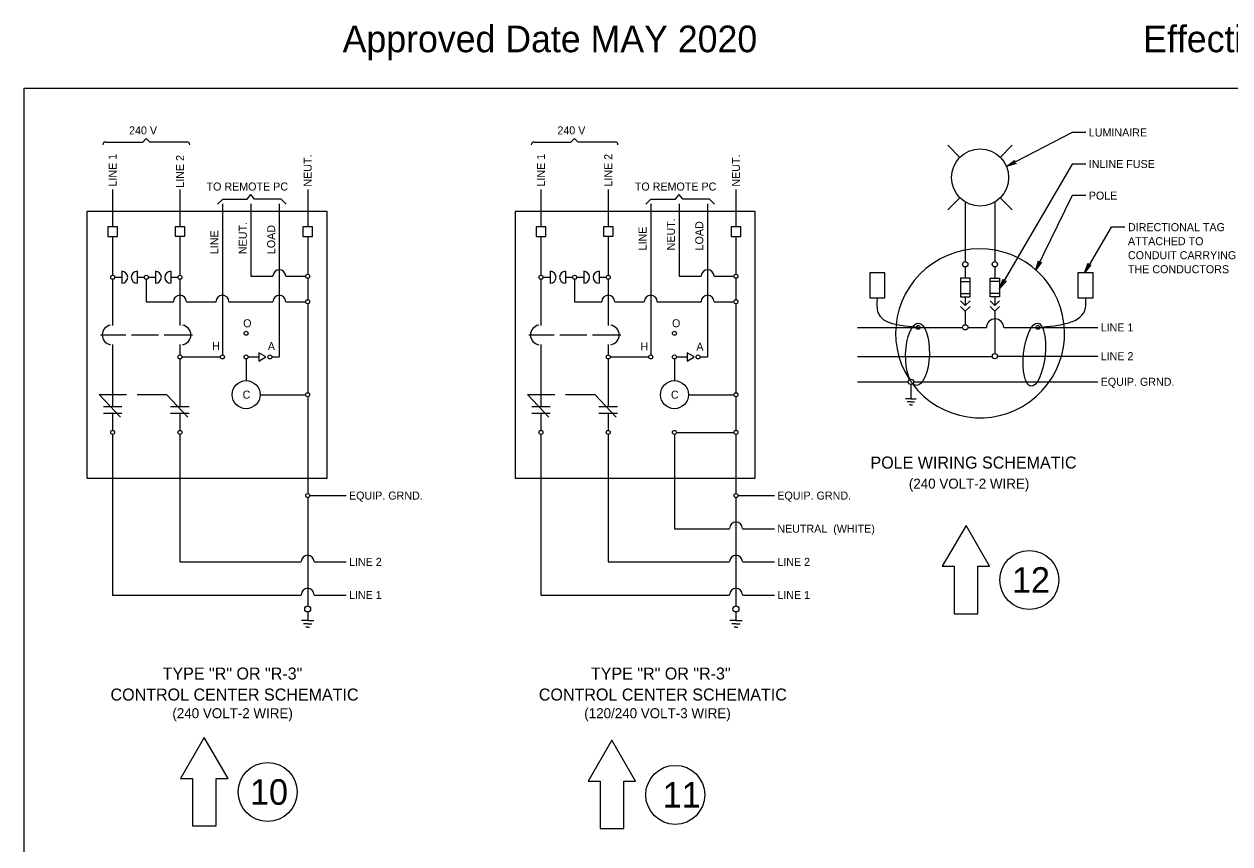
# Model space of a CAD drawing. Extents: x 99981 to 128681, y 99783 to 102182.
# Drawn here: x 120381 to 122189, y 100954 to 102182 of the extents above; entities that cross this region are included whole.
import ezdxf

# ---------------------------------------------------------------- set-up
doc = ezdxf.new("R2010")
doc.units = 0
for name, color, linetype in [('Default', 7, 'Continuous'), ('Level 1', 7, 'Continuous'), ('RD Lighting', 7, 'Continuous'), ('RD Standard Plans Active', 7, 'Continuous')]:
    doc.layers.add(name, color=color, linetype=linetype)

msp = doc.modelspace()

# ---------------------------------------------------------------- linework, layer by layer
at = {"layer": 'Default'}
msp.add_lwpolyline([(120381.4, 102086.3), (123581.1, 102086.3), (123581.1, 99886.7), (120381.4, 99886.7)], close=True, dxfattribs=at)
at = {"layer": 'Level 1'}
for p, q in [((120559.1, 102005.5), (120564.5, 102010.9)), ((120569.8, 102005.5), (120564.5, 102010.9)), ((121201.1, 102005.5), (121206.5, 102010.9)), ((121211.9, 102005.5), (121206.5, 102010.9)), ((121952.2, 102019.8), (121853.8, 101968.7)), ((121972.8, 102019.8), (121952.2, 102019.8)), ((120503.4, 102005.5), (120559.1, 102005.5)), ((120625.5, 102005.5), (120569.8, 102005.5)), ((121145.5, 102005.5), (121201.1, 102005.5)), ((121267.5, 102005.5), (121211.9, 102005.5)), ((121784, 101982.5), (121766, 102000.6)), ((121844.5, 101982.5), (121862.6, 102000.6)), ((121952.2, 101972.5), (121843.5, 101786)), ((121972.8, 101972.5), (121952.2, 101972.5)), ((120514.1, 101934.2), (120514.1, 101878.3)), ((120614.9, 101934.2), (120614.9, 101878.3)), ((120806.4, 101934.2), (120806.4, 101878.3)), ((121156.1, 101934.2), (121156.1, 101878.3)), ((121256.9, 101934.2), (121256.9, 101878.3)), ((121448.4, 101934.2), (121448.4, 101878.3)), ((120671.4, 101912.2), (120679, 101919.8)), ((120679, 101919.8), (120715.6, 101919.8)), ((120715.6, 101919.8), (120721, 101926.8)), ((120726.5, 101919.8), (120721, 101926.8)), ((120766.7, 101919.8), (120726.5, 101919.8)), ((120774.3, 101912.2), (120766.7, 101919.8)), ((121313.4, 101912.2), (121321, 101919.8)), ((121321, 101919.8), (121357.6, 101919.8)), ((121357.6, 101919.8), (121363, 101926.8)), ((121368.5, 101919.8), (121363, 101926.8)), ((121408.7, 101919.8), (121368.5, 101919.8)), ((121416.3, 101912.2), (121408.7, 101919.8)), ((121766, 101903.9), (121784, 101922)), ((121862.6, 101903.9), (121844.5, 101922)), ((121952.2, 101925.2), (121897.8, 101813.9)), ((121972.8, 101925.2), (121952.2, 101925.2)), ((120678.7, 101912.9), (120678.7, 101686.4)), ((120721.3, 101912.9), (120721.3, 101804.3)), ((120763.9, 101912.9), (120763.9, 101683.4)), ((121320.7, 101912.9), (121320.7, 101686.4)), ((121363.3, 101912.9), (121363.3, 101804.3)), ((121405.9, 101912.9), (121405.9, 101683.4)), ((121792.1, 101915.7), (121792.1, 101826.3)), ((121836.4, 101915.7), (121836.4, 101826.3)), ((120514.1, 101863.9), (120514.1, 101805.8)), ((120614.9, 101864.2), (120614.9, 101805.8)), ((120806.4, 101864.2), (120806.4, 101807.3)), ((121156.1, 101863.9), (121156.1, 101805.8)), ((121256.9, 101864.2), (121256.9, 101805.8)), ((121448.4, 101864.2), (121448.4, 101807.3)), ((122011, 101877.9), (121970.7, 101809.7)), ((122031.5, 101877.9), (122011, 101877.9)), ((120527.7, 101811.8), (120527.7, 101793.9)), ((120550.9, 101811.8), (120550.9, 101793.9)), ((120578.1, 101811.8), (120578.1, 101793.9)), ((120601.2, 101811.8), (120601.2, 101793.9)), ((121169.8, 101811.8), (121169.8, 101793.9)), ((121192.9, 101811.8), (121192.9, 101793.9)), ((121220.1, 101811.8), (121220.1, 101793.9)), ((121243.2, 101811.8), (121243.2, 101793.9)), ((121792.1, 101818.3), (121792.1, 101801.8)), ((121836.4, 101818.3), (121836.4, 101801.8)), ((120514.1, 101799.9), (120514.1, 101730.5)), ((120517.1, 101802.8), (120527.7, 101802.8)), ((120550.9, 101802.8), (120561.5, 101802.8)), ((120564.5, 101799.9), (120564.5, 101766.2)), ((120567.5, 101802.8), (120578.1, 101802.8)), ((120601.2, 101802.8), (120611.9, 101802.8)), ((120614.9, 101799.9), (120614.9, 101730.5)), ((120721.3, 101804.3), (120754.1, 101804.3)), ((120773.7, 101804.3), (120803.4, 101804.3)), ((120806.4, 101801.3), (120806.4, 101769.2)), ((121156.1, 101799.9), (121156.1, 101730.5)), ((121159.1, 101802.8), (121169.8, 101802.8)), ((121192.9, 101802.8), (121203.5, 101802.8)), ((121206.5, 101799.9), (121206.5, 101766.2)), ((121209.5, 101802.8), (121220.1, 101802.8)), ((121243.2, 101802.8), (121253.9, 101802.8)), ((121256.9, 101799.9), (121256.9, 101730.5)), ((121363.3, 101804.3), (121396.1, 101804.3)), ((121415.7, 101804.3), (121445.5, 101804.3)), ((121448.4, 101801.3), (121448.4, 101769.2)), ((121785, 101796.4), (121799.2, 101796.4)), ((121843.5, 101796.4), (121829.3, 101796.4)), ((121785, 101778.4), (121799.2, 101778.4)), ((121792.1, 101773.3), (121792.1, 101760.6)), ((121843.5, 101778.4), (121829.3, 101778.4)), ((121836.4, 101773.3), (121836.4, 101760.6)), ((120564.5, 101766.2), (120605.1, 101766.2)), ((120624.6, 101766.2), (120669, 101766.2)), ((120688.4, 101766.2), (120754.1, 101766.2)), ((120773.6, 101766.2), (120803.4, 101766.2)), ((120806.4, 101763.2), (120806.4, 101629.9)), ((121206.5, 101766.2), (121247.1, 101766.2)), ((121266.6, 101766.2), (121311, 101766.2)), ((121330.5, 101766.2), (121396.1, 101766.2)), ((121415.6, 101766.2), (121445.5, 101766.2)), ((121448.4, 101763.2), (121448.4, 101629.9)), ((121792.1, 101752.1), (121792.1, 101731.7)), ((121836.4, 101752.1), (121836.4, 101688.5)), ((121630.6, 101727.6), (121788.2, 101727.6)), ((121796.1, 101727.6), (121823.8, 101727.6)), ((121849.7, 101727.6), (121990.6, 101727.6)), ((120496, 101716.4), (120533.9, 101716.4)), ((120514.1, 101702.2), (120514.1, 101609.2)), ((120542.5, 101716.4), (120583, 101716.4)), ((120591.4, 101716.4), (120633.8, 101716.4)), ((120614.9, 101702.2), (120614.9, 101686.4)), ((121138, 101716.4), (121175.9, 101716.4)), ((121156.1, 101702.2), (121156.1, 101609.2)), ((121184.5, 101716.4), (121225, 101716.4)), ((121233.4, 101716.4), (121275.8, 101716.4)), ((121256.9, 101702.2), (121256.9, 101686.4)), ((120617.8, 101683.4), (120675.7, 101683.4)), ((120717.2, 101683.4), (120733.2, 101683.4)), ((120752.6, 101683.4), (120763.9, 101683.4)), ((121259.8, 101683.4), (121317.7, 101683.4)), ((121359.2, 101683.4), (121375.2, 101683.4)), ((121394.7, 101683.4), (121405.9, 101683.4)), ((121630.6, 101684.3), (121832.5, 101684.3)), ((121840.4, 101684.6), (121990.6, 101684.6)), ((120614.9, 101680.5), (120614.9, 101609.2)), ((120714.2, 101680.5), (120714.2, 101647.9)), ((121256.9, 101680.5), (121256.9, 101609.2)), ((121356.2, 101680.5), (121356.2, 101647.9)), ((121630.6, 101646.2), (121706.7, 101646.2)), ((121714.6, 101646.2), (121990.6, 101646.2)), ((120494.1, 101627.2), (120525.9, 101593.3)), ((120494.1, 101627.2), (120534.9, 101627.2)), ((120550.7, 101627.2), (120594.8, 101627.2)), ((120594.8, 101627.2), (120626.6, 101593.3)), ((120735.2, 101626.9), (120803.4, 101626.9)), ((121136.1, 101627.2), (121167.9, 101593.3)), ((121136.1, 101627.2), (121177, 101627.2)), ((121192.7, 101627.2), (121236.8, 101627.2)), ((121236.8, 101627.2), (121268.6, 101593.3)), ((121377.2, 101626.9), (121445.5, 101626.9)), ((121710.7, 101642.2), (121710.7, 101620.5)), ((120500.2, 101609.2), (120528, 101609.2)), ((120600.9, 101609.2), (120628.8, 101609.2)), ((120806.4, 101623.5), (120806.4, 101479.1)), ((121142.2, 101609.2), (121170.1, 101609.2)), ((121242.9, 101609.2), (121270.8, 101609.2)), ((121448.4, 101623.5), (121448.4, 101573.4)), ((121710.6, 101620.5), (121702.6, 101620.5)), ((121710.6, 101616.3), (121705.2, 101616.3)), ((121710.6, 101611.9), (121708.3, 101611.9)), ((121710.7, 101620.5), (121718.7, 101620.5)), ((121710.7, 101616.3), (121716.1, 101616.3)), ((121710.7, 101611.9), (121713, 101611.9)), ((120500.2, 101599.2), (120528, 101599.2)), ((120514.1, 101599.2), (120514.1, 101573.4)), ((120600.9, 101599.2), (120628.8, 101599.2)), ((120614.9, 101599.2), (120614.9, 101573.4)), ((121142.2, 101599.2), (121170.1, 101599.2)), ((121156.1, 101599.2), (121156.1, 101573.4)), ((121242.9, 101599.2), (121270.8, 101599.2)), ((121256.9, 101599.2), (121256.9, 101573.4)), ((120514.1, 101567.4), (120514.1, 101326.7)), ((120614.9, 101567.4), (120614.9, 101376.4)), ((121156.1, 101567.4), (121156.1, 101326.7)), ((121256.9, 101567.4), (121256.9, 101376.4)), ((121356.2, 101567.4), (121356.2, 101426.1)), ((121359.2, 101570.4), (121445.5, 101570.4)), ((121448.4, 101567.4), (121448.4, 101478.7)), ((120806.4, 101472.7), (120806.4, 101310.3)), ((120809.4, 101475.7), (120863.9, 101475.7)), ((121448.4, 101472.7), (121448.4, 101310.3)), ((121451.4, 101475.7), (121505.9, 101475.7)), ((121356.2, 101426.1), (121438.7, 101426.1)), ((121458.1, 101426.1), (121505.9, 101426.1)), ((120614.9, 101376.4), (120796.7, 101376.4)), ((120816.1, 101376.4), (120863.9, 101376.4)), ((121256.9, 101376.4), (121438.7, 101376.4)), ((121458.1, 101376.4), (121505.9, 101376.4)), ((120514.1, 101326.7), (120796.7, 101326.7)), ((120816.1, 101326.7), (120863.9, 101326.7)), ((121156.1, 101326.7), (121438.7, 101326.7)), ((121458.1, 101326.7), (121505.9, 101326.7)), ((120806.4, 101288.3), (120797.2, 101288.4)), ((120806.4, 101283.5), (120800.1, 101283.5)), ((120806.4, 101301.1), (120806.4, 101288.3)), ((120806.4, 101288.3), (120815.7, 101288.3)), ((120806.4, 101283.5), (120812.7, 101283.5)), ((121448.4, 101288.3), (121439.2, 101288.4)), ((121448.4, 101283.5), (121442.1, 101283.5)), ((121448.4, 101301.1), (121448.4, 101288.3)), ((121448.4, 101288.3), (121457.7, 101288.3)), ((121448.4, 101283.5), (121454.7, 101283.5)), ((120806.4, 101278.4), (120803.7, 101278.4)), ((120806.4, 101278.4), (120809.1, 101278.4)), ((121448.4, 101278.4), (121445.7, 101278.4)), ((121448.4, 101278.4), (121451.1, 101278.4))]:
    msp.add_line(p, q, dxfattribs=at)
for points in [[(121868.2, 101973.3), (121853.8, 101968.7), (121865.9, 101977.8), (121865, 101974.5)], [(120475.6, 101501.7), (120835.4, 101501.7), (120835.4, 101901.5), (120475.6, 101901.5)], [(121117.6, 101501.7), (121477.4, 101501.7), (121477.4, 101901.5), (121117.6, 101901.5)], [(120507.1, 101864.1), (120521.3, 101864.1), (120521.3, 101878.2), (120507.1, 101878.2)], [(120607.9, 101864.2), (120622.1, 101864.2), (120622.1, 101878.3), (120607.9, 101878.3)], [(120799.3, 101864), (120813.5, 101864), (120813.5, 101878.2), (120799.3, 101878.2)], [(121149.1, 101864.1), (121163.3, 101864.1), (121163.3, 101878.2), (121149.1, 101878.2)], [(121249.9, 101864.2), (121264.1, 101864.2), (121264.1, 101878.3), (121249.9, 101878.3)], [(121441.3, 101864), (121455.5, 101864), (121455.5, 101878.2), (121441.3, 101878.2)], [(121906.1, 101825.5), (121897.8, 101813.9), (121901.8, 101827.6), (121903, 101824.6)], [(121671.5, 101771.9), (121671.5, 101809.7), (121648.8, 101809.7), (121648.8, 101771.9)], [(121983.6, 101771.9), (121983.6, 101809.7), (121960.9, 101809.7), (121960.9, 101771.9)], [(121980.5, 101821.3), (121970.7, 101809.7), (121976.1, 101823.8), (121977.1, 101820.5)], [(121785, 101773.3), (121799.2, 101773.3), (121799.2, 101801.7), (121785, 101801.7)], [(121843.5, 101773.3), (121829.3, 101773.3), (121829.3, 101801.7), (121843.5, 101801.7)], [(121853.2, 101797.6), (121843.5, 101786), (121848.8, 101800.2), (121849.9, 101796.9)], [(120743.8, 101683.4), (120733.2, 101689.6), (120733.2, 101677.3)], [(121385.8, 101683.4), (121375.2, 101689.6), (121375.2, 101677.3)]]:
    msp.add_lwpolyline(points, close=True, dxfattribs=at)
for points in [[(121785, 101767.7), (121792.1, 101760.6), (121799.2, 101767.7)], [(121785, 101759.2), (121792.1, 101752.1), (121799.2, 101759.2)], [(121843.5, 101767.7), (121836.4, 101760.6), (121829.3, 101767.7)], [(121843.5, 101759.2), (121836.4, 101752.1), (121829.3, 101759.2)]]:
    msp.add_lwpolyline(points, dxfattribs=at)
for centre, radius in [((121814.3, 101952.3), 42.8), ((121792.1, 101822.3), 3.97), ((121836.4, 101822.3), 3.97), ((120514.1, 101802.8), 2.98), ((120564.5, 101802.8), 2.98), ((120614.9, 101802.8), 2.98), ((120806.4, 101804.3), 2.98), ((121156.1, 101802.8), 2.98), ((121206.5, 101802.8), 2.98), ((121256.9, 101802.8), 2.98), ((121448.4, 101804.3), 2.98), ((120806.4, 101766.2), 2.98), ((121448.4, 101766.2), 2.98), ((120714.2, 101718.9), 2.98), ((121356.2, 101718.9), 2.98), ((121721.3, 101727.7), 2.84), ((121792.1, 101727.8), 3.97), ((121901, 101727.7), 2.84), ((120614.9, 101683.4), 2.98), ((120678.7, 101683.4), 2.98), ((120714.2, 101683.4), 2.98), ((120749.7, 101683.4), 2.98), ((121256.9, 101683.4), 2.98), ((121320.7, 101683.4), 2.98), ((121356.2, 101683.4), 2.98), ((121391.7, 101683.4), 2.98), ((121836.4, 101684.6), 3.97), ((120714.2, 101626.9), 21), ((121356.2, 101626.9), 21), ((121710.7, 101646.2), 3.97), ((120806.4, 101626.9), 2.98), ((121448.4, 101626.9), 2.98), ((120514.1, 101570.4), 2.98), ((120614.9, 101570.4), 2.98), ((121156.1, 101570.4), 2.98), ((121256.9, 101570.4), 2.98), ((121356.2, 101570.4), 2.98), ((121448.4, 101570.4), 2.98), ((120806.4, 101475.7), 2.98), ((121448.4, 101475.7), 2.98), ((120806.4, 101305.8), 4.47), ((121448.4, 101305.8), 4.47)]:
    msp.add_circle(centre, radius, dxfattribs=at)
for centre, radius, start, end in [((120503.5, 102001.4), 4.15, 89.2769, 178.8505), ((120625.4, 102001.4), 4.15, 1.1495, 90.7231), ((121145.6, 102001.4), 4.15, 89.2769, 178.8505), ((121267.4, 102001.4), 4.15, 1.1495, 90.7231), ((121814.3, 101718.8), 126.6, 216.8263, 213.2275), ((120527.7, 101802.8), 8.96, 270, 90), ((120550.9, 101802.8), 8.96, 90, 270), ((120578.1, 101802.8), 8.96, 270, 90), ((120601.2, 101802.8), 8.96, 90, 270), ((120763.9, 101804.3), 9.72, 0, 180), ((121169.8, 101802.8), 8.96, 270, 90), ((121192.9, 101802.8), 8.96, 90, 270), ((121220.1, 101802.8), 8.96, 270, 90), ((121243.2, 101802.8), 8.96, 90, 270), ((121405.9, 101804.3), 9.72, 0, 180), ((120614.9, 101766.2), 9.72, 0, 180), ((120678.7, 101766.2), 9.72, 0, 180), ((120763.9, 101766.2), 9.72, 0, 180), ((121256.9, 101766.2), 9.72, 0, 180), ((121320.7, 101766.2), 9.72, 0, 180), ((121405.9, 101766.2), 9.72, 0, 180), ((121836.8, 101727.4), 13, 0, 180), ((120513.3, 101716.4), 14.9, 99.986, 260.014), ((120616.4, 101716.4), 14.9, 279.986, 80.014), ((121155.3, 101716.4), 14.9, 99.986, 260.014), ((121258.4, 101716.4), 14.9, 279.986, 80.014), ((121448.4, 101426.4), 9.72, 0, 180), ((120806.4, 101376.7), 9.72, 0, 180), ((121448.4, 101376.7), 9.72, 0, 180), ((120806.4, 101327.1), 9.72, 0, 180), ((121448.4, 101327.1), 9.72, 0, 180)]:
    msp.add_arc(centre, radius, start, end, dxfattribs=at)
for centre, major_axis, ratio in [((121895.6, 101686.9), (-5.1, -47.3), 0.339542), ((121720.5, 101687.5), (-1.5, -46.7), 0.380534)]:
    msp.add_ellipse(centre, major_axis=major_axis, ratio=ratio, dxfattribs=at)
for points in [[(121721.3, 101727.7), (121661.7, 101749.9), (121660.3, 101770.3)], [(121901, 101727.7), (121972.2, 101756.9), (121972.6, 101770.8)]]:
    msp.add_spline(points, degree=3, dxfattribs=at)
at = {"layer": 'RD Lighting'}
for points in [[(121793.2, 101431.1), (121757.7, 101369.7), (121775.4, 101369.7), (121775.4, 101298.7), (121810.9, 101298.7), (121810.9, 101369.7), (121828.6, 101369.7)], [(120651.5, 101113.4), (120616, 101052), (120633.8, 101052), (120633.8, 100981), (120669.3, 100981), (120669.3, 101052), (120687, 101052)], [(121262.4, 101109.2), (121226.9, 101047.7), (121244.7, 101047.7), (121244.7, 100976.8), (121280.1, 100976.8), (121280.1, 101047.7), (121297.9, 101047.7)]]:
    msp.add_lwpolyline(points, close=True, dxfattribs=at)
for centre in [(121888, 101349.3), (120746.4, 101031.6), (121357.3, 101027.3)]:
    msp.add_circle(centre, 44.2, dxfattribs=at)

# ---------------------------------------------------------------- texts
at = {"layer": 'Level 1'}
for s, height, p in [('240 V', 12, (120538.7, 102016.9)), ('240 V', 12, (121180.7, 102016.9)), (' LUMINAIRE', 12, (121972.8, 102013.8)), (' INLINE FUSE', 12, (121972.8, 101966.5)), ('TO REMOTE PC', 12, (120654.8, 101932.8)), ('TO REMOTE PC', 12, (121296.8, 101932.8)), (' POLE', 12, (121972.8, 101919.2)), (' DIRECTIONAL TAG', 12, (122031.5, 101871.9)), (' ATTACHED TO', 12, (122031.5, 101850.9)), (' CONDUIT CARRYING', 12, (122031.5, 101829.9)), (' THE CONDUCTORS', 12, (122031.5, 101808.9)), ('O', 12, (120709.7, 101727.9)), ('O', 12, (121352.5, 101727.9)), (' LINE 1', 12, (121990.6, 101721.6)), ('H', 12, (120663.2, 101693.7)), ('A', 12, (120746.7, 101693.6)), ('H', 12, (121305.2, 101693.1)), ('A', 12, (121389, 101692.9)), (' LINE 2', 12, (121990.6, 101678.6)), (' EQUIP. GRND.', 12, (121990.6, 101640.2)), ('C', 12, (120708.9, 101620.9)), ('C', 12, (121350.9, 101620.9)), ('POLE WIRING SCHEMATIC', 18, (121650, 101516.2)), ('(240 VOLT-2 WIRE)', 15, (121707.5, 101486.1)), (' EQUIP. GRND.', 12, (120863.9, 101469.7)), (' EQUIP. GRND.', 12, (121505.9, 101469.7)), (' NEUTRAL  (WHITE)', 12, (121505.9, 101420.1)), (' LINE 2', 12, (120863.9, 101370.4)), (' LINE 2', 12, (121505.9, 101370.4)), (' LINE 1', 12, (120863.9, 101320.7)), (' LINE 1', 12, (121505.9, 101320.7)), ('TYPE "R" OR "R-3"', 18, (120589, 101200.1)), ('TYPE "R" OR "R-3"', 18, (121231, 101200.1)), ('CONTROL CENTER SCHEMATIC', 18, (120510.9, 101168.6)), ('CONTROL CENTER SCHEMATIC', 18, (121152.9, 101168.6)), ('(240 VOLT-2 WIRE)', 15, (120603.6, 101142.1)), ('(120/240 VOLT-3 WIRE)', 15, (121221, 101142.1))]:
    msp.add_text(s, height=height, dxfattribs=at).set_placement(p)
for s, p in [(' LINE 1', (120520.1, 101934.2)), (' LINE 2', (120621.1, 101932.5)), (' NEUT.', (120812.4, 101934.2)), (' LINE 1', (121162.1, 101934.2)), (' LINE 2', (121262.9, 101934.2)), (' NEUT.', (121454.4, 101934.2)), ('NEUT.', (120715.1, 101837.5)), ('LOAD', (120757.7, 101837.5)), ('NEUT.', (121356.8, 101843.1)), ('LOAD', (121399.4, 101843.1)), ('LINE', (120672.5, 101837.5)), ('LINE', (121314.3, 101843.1))]:
    msp.add_text(s, height=12, rotation=90, dxfattribs=at).set_placement(p)
at = {"layer": 'RD Lighting'}
for s, p in [('12', (121862, 101330.1)), ('10', (120720, 101012.4)), ('11', (121338.7, 101008.2))]:
    msp.add_text(s, height=38.31, dxfattribs=at).set_placement(p)
at = {"layer": 'RD Standard Plans Active'}
for s, p in [('Approved Date MAY 2020', (120858.8, 102140)), ('Effective Letting Date current', (122058.8, 102140))]:
    msp.add_text(s, height=40, dxfattribs=at).set_placement(p)

doc.saveas('drawing.dxf')
